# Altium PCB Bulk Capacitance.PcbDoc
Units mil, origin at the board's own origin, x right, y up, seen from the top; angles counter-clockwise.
Board outline 5000 x 5399.89 mil, 4 copper layers (Top Layer, Layer 1, Layer 2, Bottom Layer), stack 91.999 mil thick; 30 components, 6 nets, 116 pads, 1 vias.
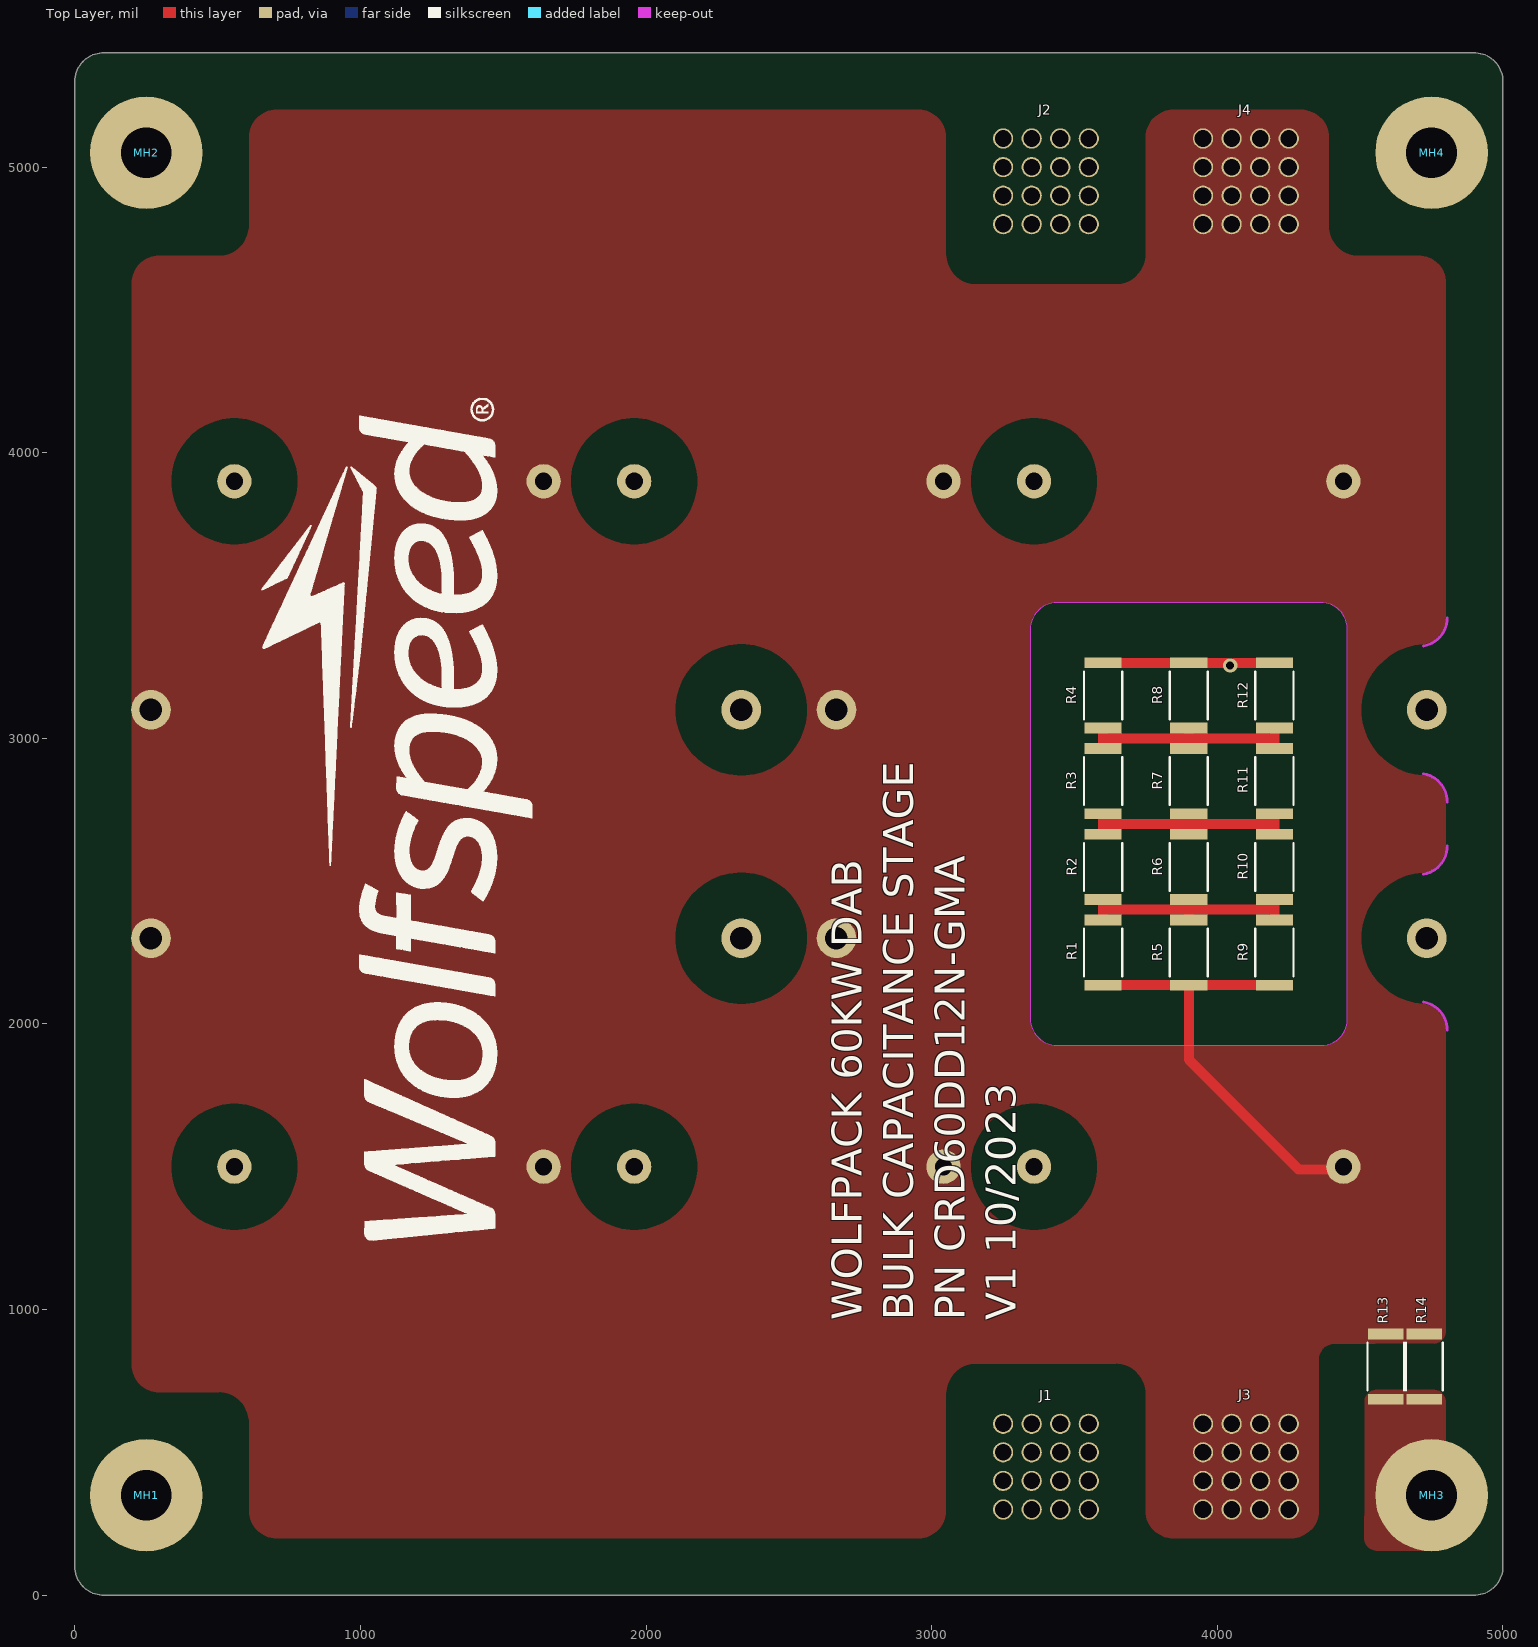
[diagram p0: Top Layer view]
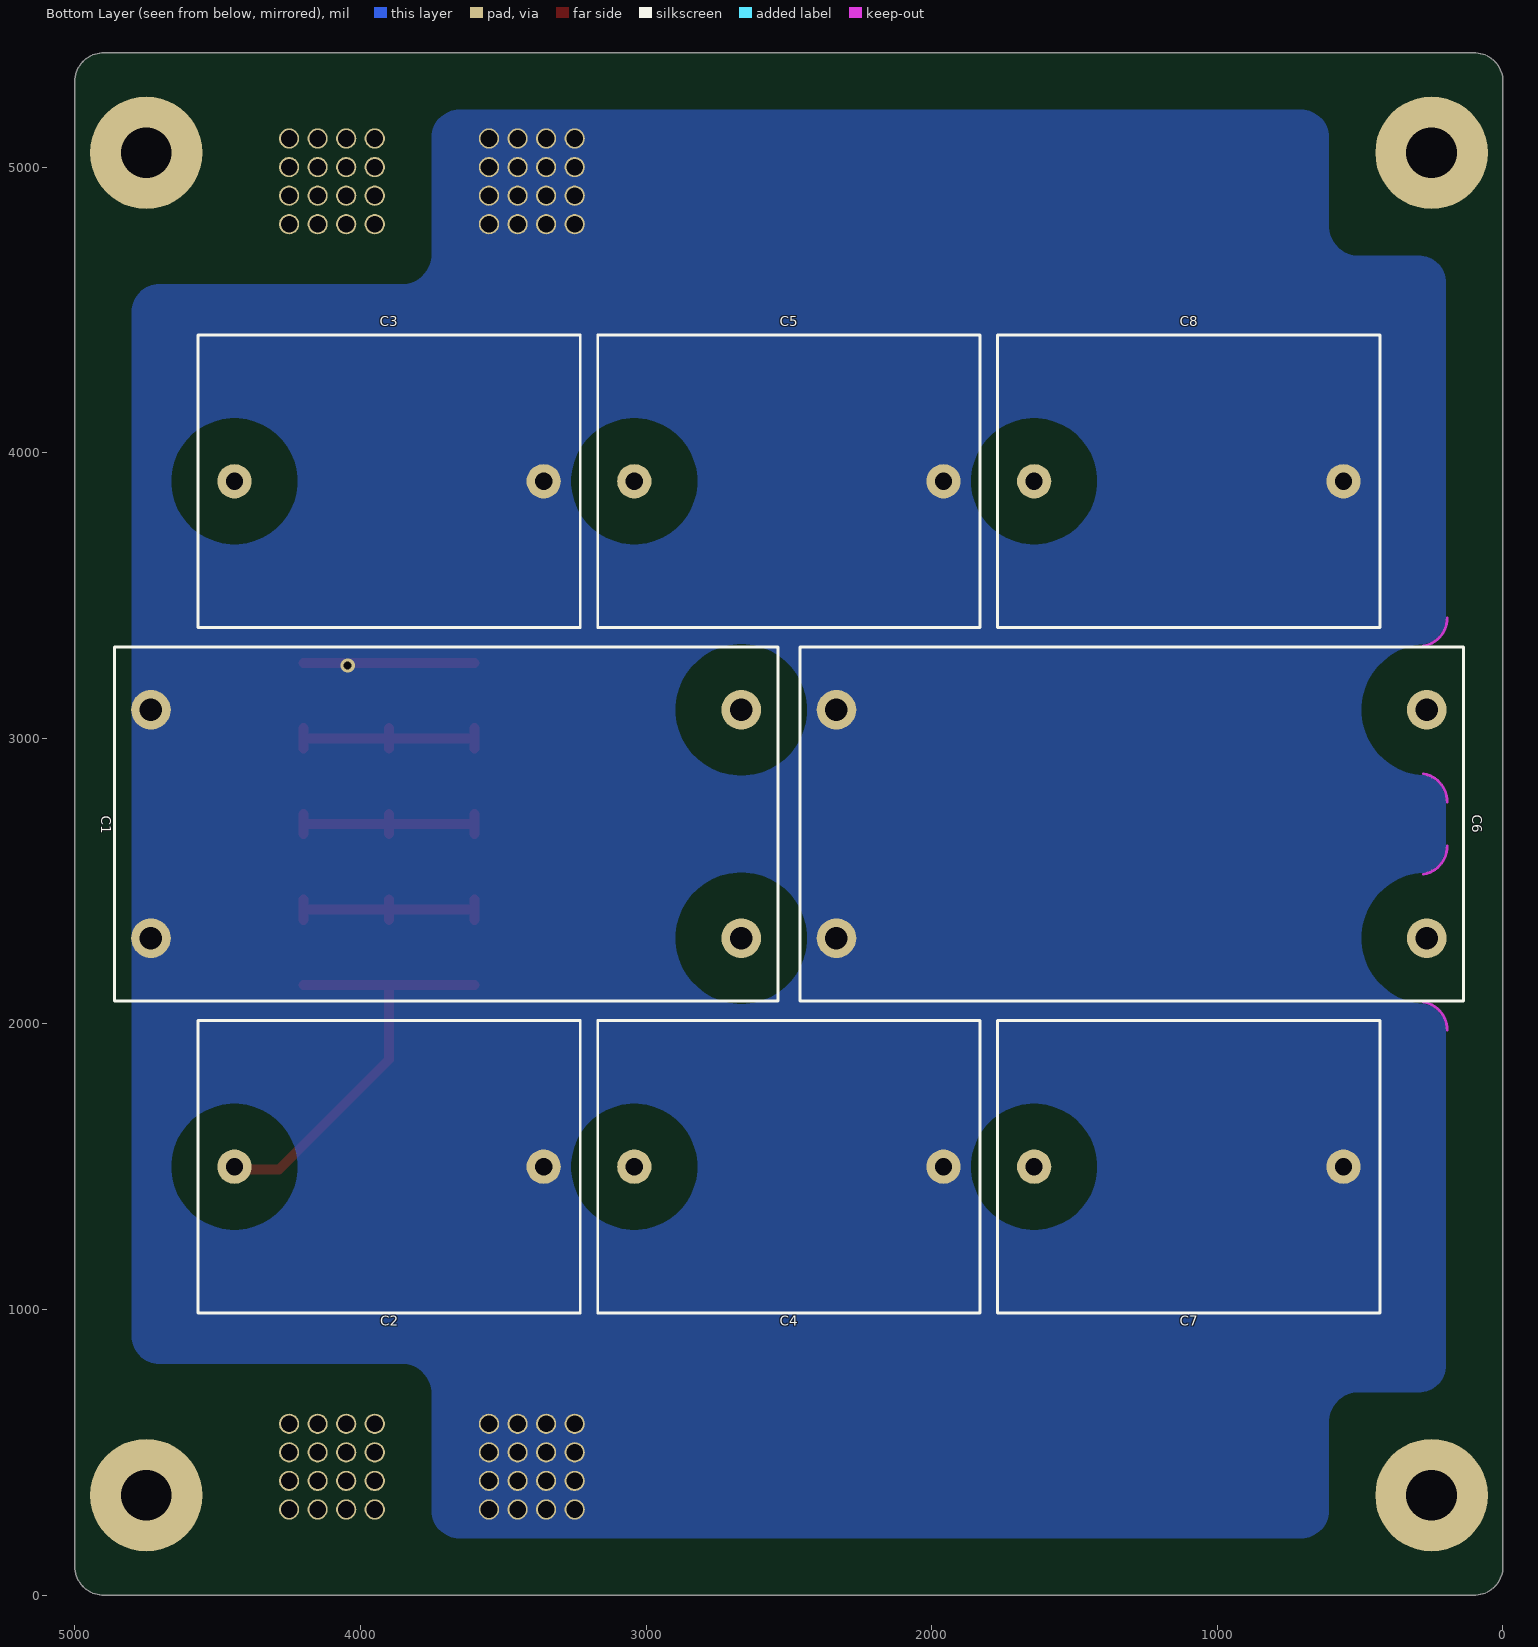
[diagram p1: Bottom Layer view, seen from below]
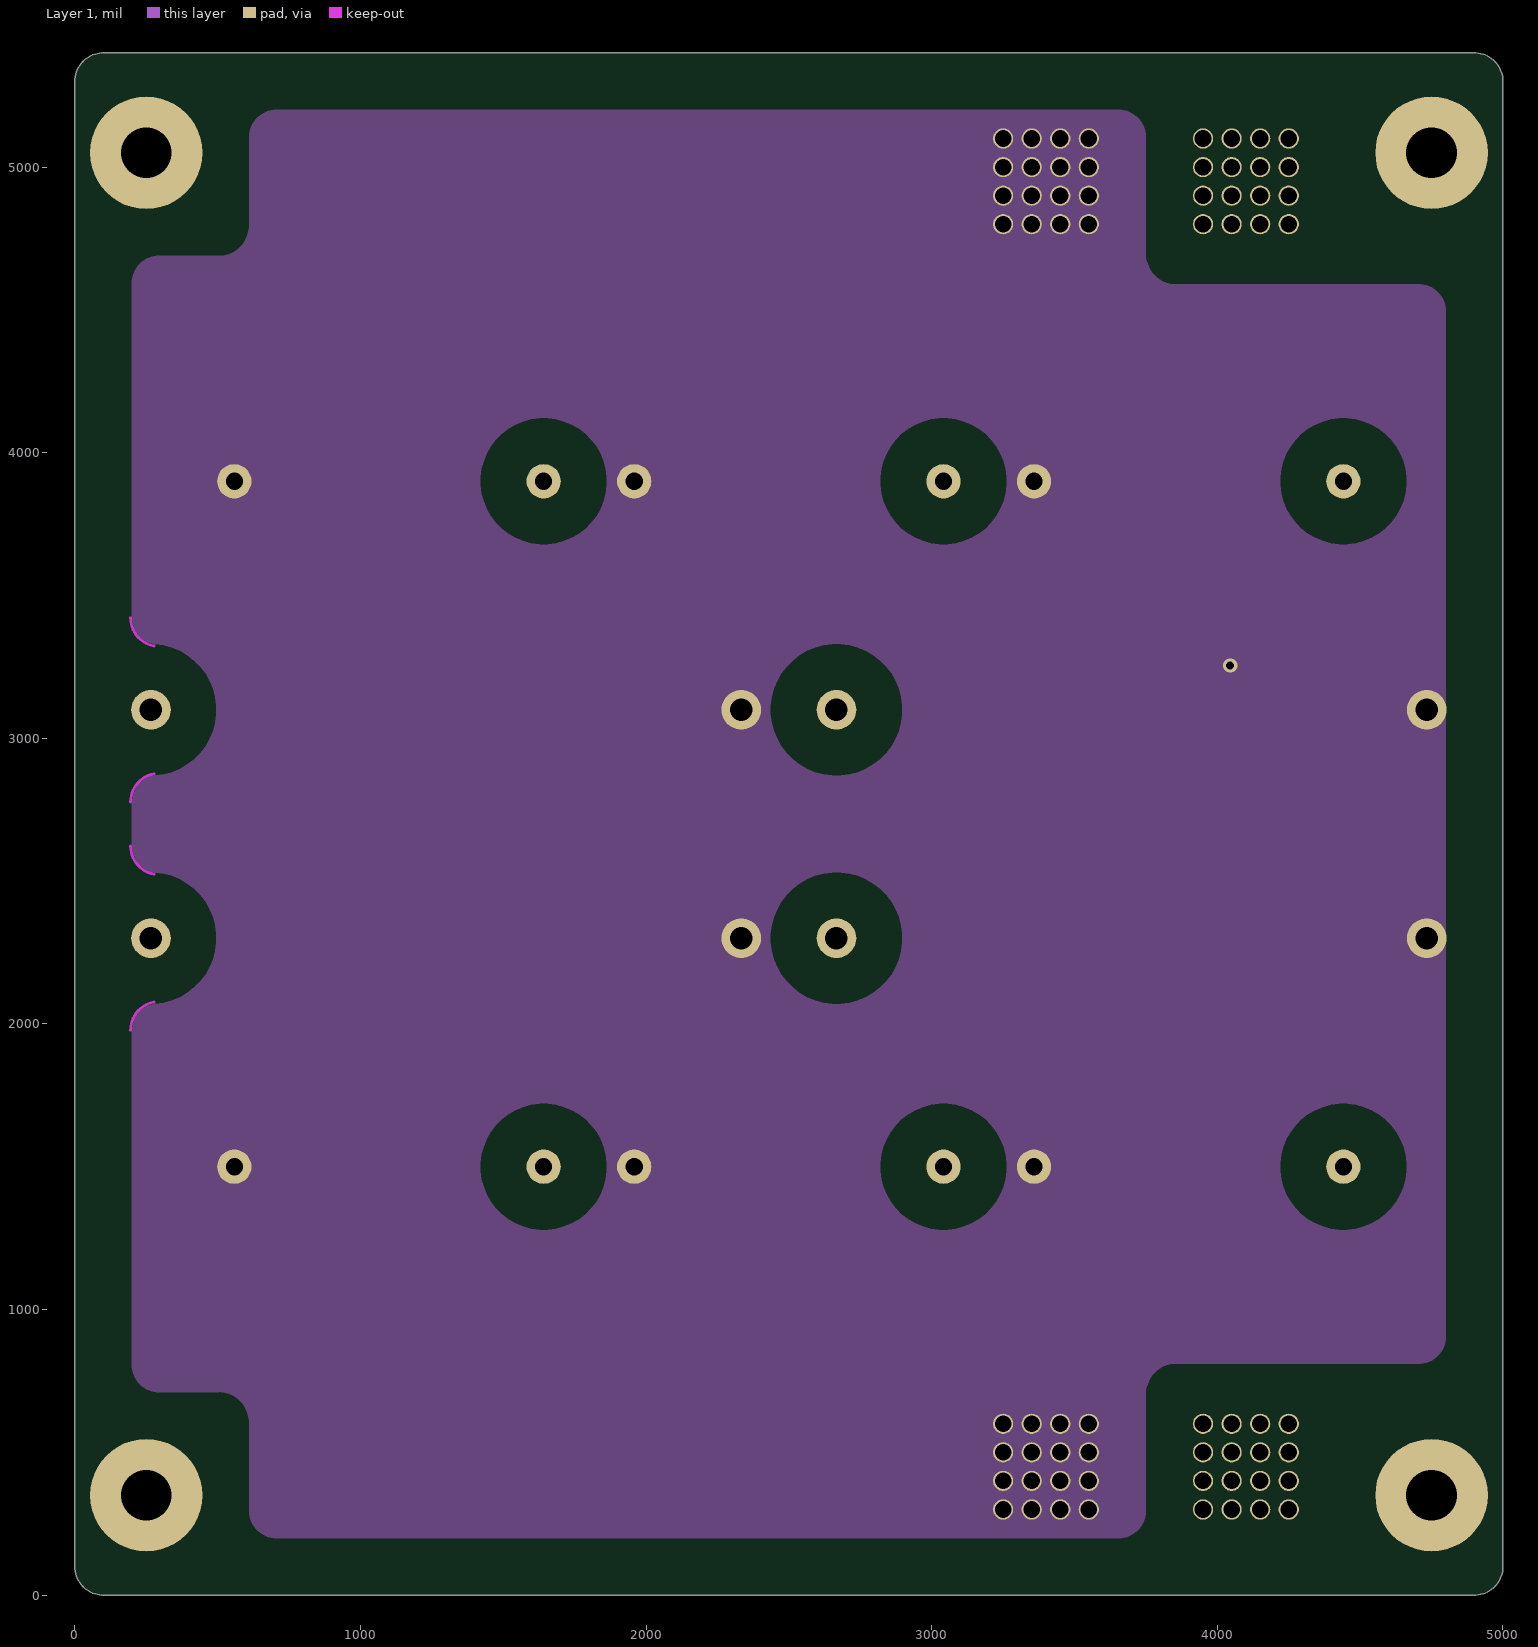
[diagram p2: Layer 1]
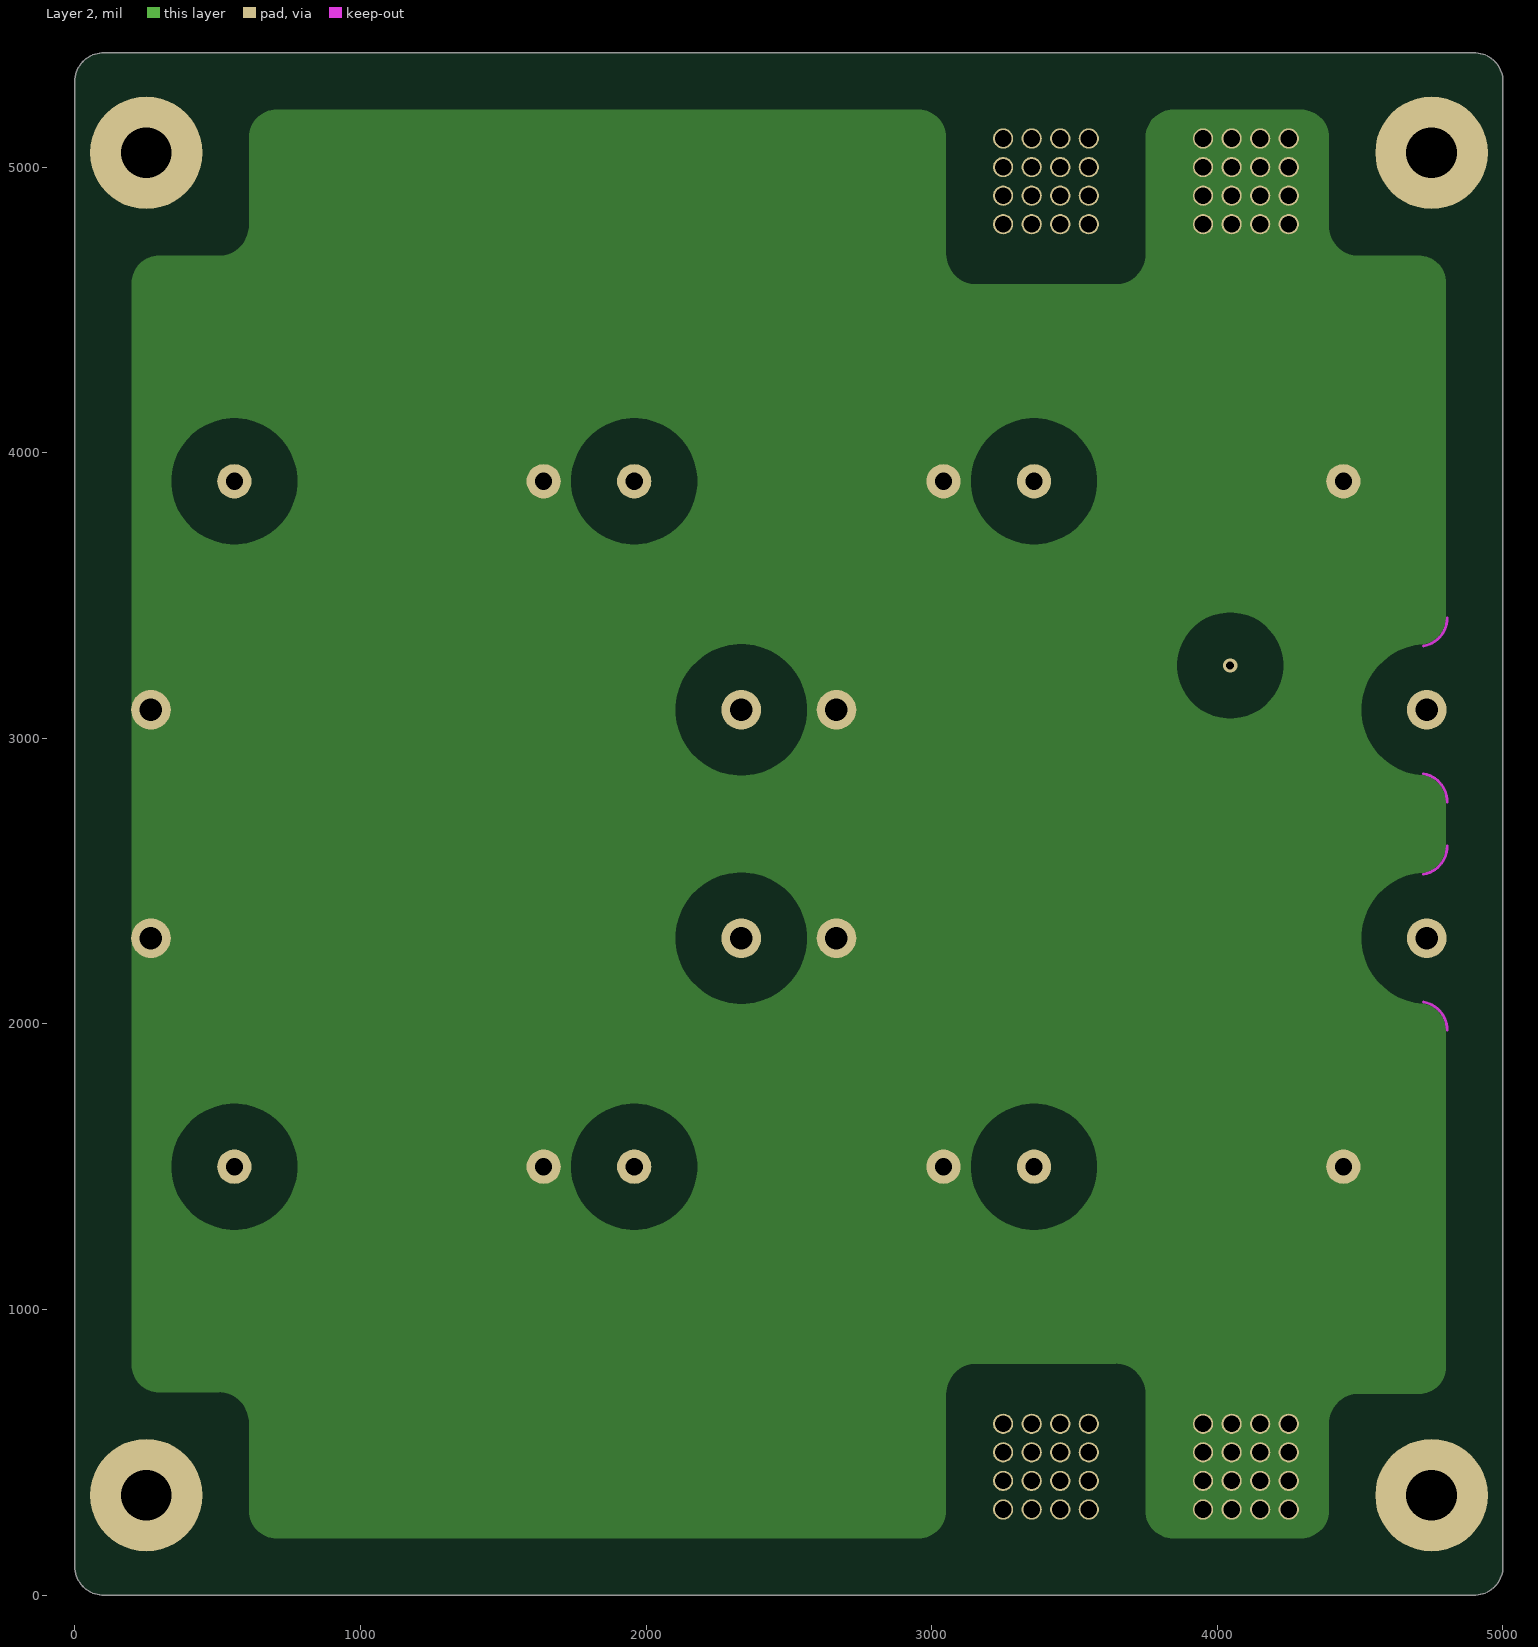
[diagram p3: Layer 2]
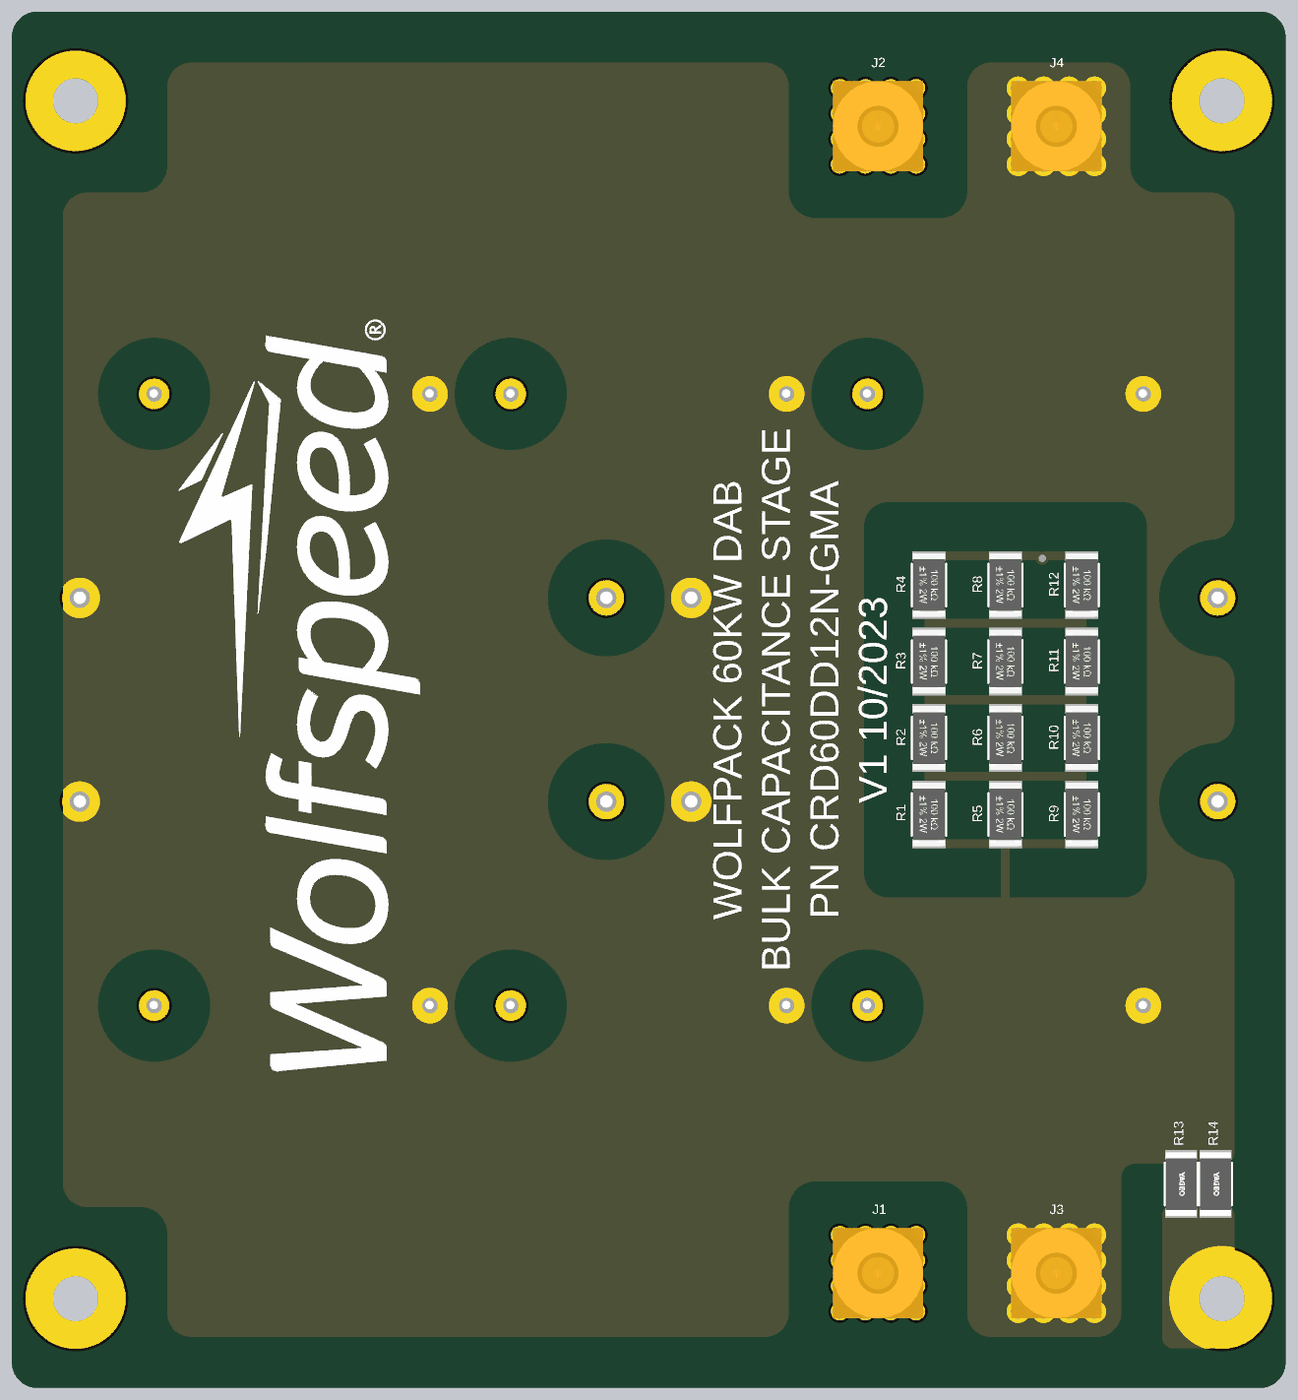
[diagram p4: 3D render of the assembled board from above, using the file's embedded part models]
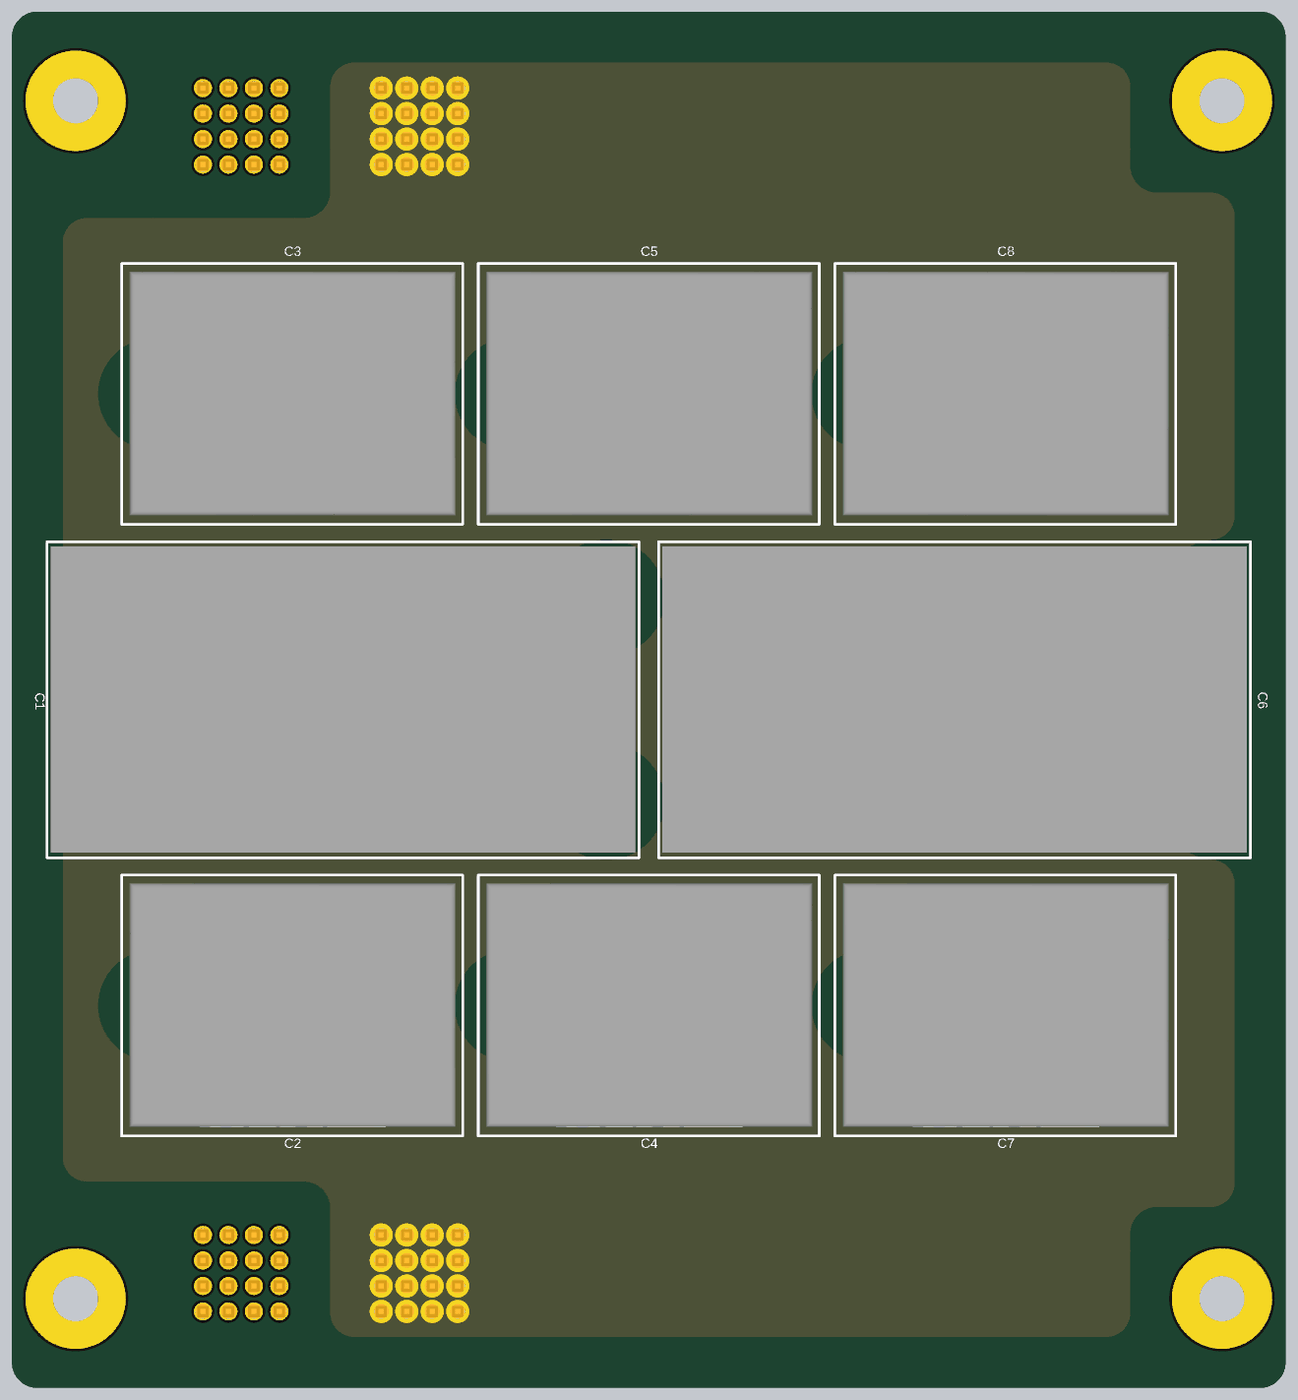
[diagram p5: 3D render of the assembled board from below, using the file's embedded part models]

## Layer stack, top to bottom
Top Solder: solder mask 0.5, Solder Resist, Dk 3.3
Top Layer: signal copper 8.2677
Dielectric 1: prepreg 2.8, PP-006, Dk 4.1
Layer 1: signal copper 8.2677
Dielectric1: core 53.328, FR-4, Dk 4.3
Layer 2: signal copper 8.2677
Dielectric 2: prepreg 2.8, PP-006, Dk 4.1
Bottom Layer: signal copper 8.2677
Bottom Solder: solder mask 0.5, Solder Resist, Dk 3.3

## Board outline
0,100 0,5300 cw(c100,5300) 103.28,5399.95 4896.72,5399.95 cw(c4900,5300) 5000,5300 5000,100 cw(c4900,100) 4896.72,0.05 103.28,0.05 cw(c100,100)

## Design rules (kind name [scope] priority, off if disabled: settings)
Clearance Keepout [IsKeepOut] p1: gap=0 ignorepadtopadclearanceinfootprint=FALSE
Clearance [All] p2: gap=160 ignorepadtopadclearanceinfootprint=FALSE
DiffPairsRouting [All] p1: maxlimit=10 minlimit=10 mostfreqgap=10 toplayer_minwidth=10 toplayer_maxwidth=10 toplayer_prefwidth=10 midlayer1_minwidth=10 midlayer1_maxwidth=10 midlayer1_prefwidth=10 midlayer2_minwidth=10 midlayer2_maxwidth=10 midlayer2_prefwidth=10 bottomlayer_minwidth=10 bottomlayer_maxwidth=10 bottomlayer_prefwidth=10 maxuncoupledlength=500
Height [All] p1: minheight=0 maxheight=2000 prefheight=500
HoleSize [All] p1: absolutevalues=TRUE maxlimit=300 minlimit=10 maxpercent=80.000 minpercent=20.000
MinimumAnnularRing [All] p1: minimumring=6
MinimumSolderMaskSliver [All] p1: minsoldermaskwidth=9
PasteMaskExpansion [All] p1: expansion=10
PlaneClearance [All] p1: clearance=15
PlaneConnect [All] p1: pad.planeconnectstyle=Relief pad.reliefexpansion=20 pad.reliefentries=4 pad.reliefconductorwidth=10 pad.reliefairgap=10 via.planeconnectstyle=Direct via.reliefexpansion=20 via.reliefentries=4 via.reliefconductorwidth=10 via.reliefairgap=10
PolygonConnect [All] p1: connectstyle=Direct reliefconductorwidth=10 reliefentries=4 polygonreliefangle="90 Angle" airgapwidth=10
RoutingVias [All] p1: holewidth=10 width=20 viastyle="Through Hole" minholewidth=10 minwidth=20 maxholewidth=30 maxwidth=50
SMDNeckDown [All] p1: percent=100.000
SilkToSilkClearance [All] p1: silktosilkclearance=9
SilkToSolderMaskClearance SilkscreenOverComponentPads [IsPad] p1: minsilkscreentomaskgap=8 clearancetoexposedcopper=TRUE
SolderMaskExpansion [All] p1: expansion=10 istentingtop=FALSE
Width [All] p1: maxlimit=50 minlimit=10 preferedwidth=10
21 further rules are at their usual default settings.

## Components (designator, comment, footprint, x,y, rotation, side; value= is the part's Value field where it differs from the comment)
C1 "C4AQQBW5240M3MJ" C4AQQBW5240M3MJ 3700,2700 r90 bottom value=24μF (schematic designator C2)
C2 "C4AQQLU4210M12J" C4AQQLU4210M12J 3900,1500 r270 bottom value=2.1μF (schematic designator C5)
C3 "C4AQQLU4210M12J" C4AQQLU4210M12J 3900,3900 r270 bottom value=2.1μF (schematic designator C8)
C4 "C4AQQLU4210M12J" C4AQQLU4210M12J 2500,1500 r270 bottom value=2.1μF
C5 "C4AQQLU4210M12J" C4AQQLU4210M12J 2500,3900 r270 bottom value=2.1μF (schematic designator C7)
C6 "C4AQQBW5240M3MJ" C4AQQBW5240M3MJ 1300,2700 r90 bottom value=24μF (schematic designator C1)
C7 "C4AQQLU4210M12J" C4AQQLU4210M12J 1100,1500 r270 bottom value=2.1μF (schematic designator C3)
C8 "C4AQQLU4210M12J" C4AQQLU4210M12J 1100,3900 r270 bottom value=2.1μF (schematic designator C6)
J1 "7461095" "7461095_chemical surface" 3400,450 r0 top value=N/A
J2 "7461095" "7461095_chemical surface" 3400,4950 r0 top value=N/A (schematic designator J3)
J3 "7461095" "7461095_chemical surface" 4100,450 r0 top value=N/A (schematic designator J2)
J4 "7461095" "7461095_chemical surface" 4100,4950 r0 top value=N/A
MH1 "MH_M4_P" MH_M4_P 250,350 r0 top value=N/A (schematic designator MH3)
MH2 "MH_M4_P" MH_M4_P 250,5050 r0 top value=N/A (schematic designator MH1)
MH3 "MH_M4_P" MH_M4_P 4750,350 r0 top value=N/A (schematic designator MH4)
MH4 "MH_M4_P" MH_M4_P 4750,5050 r0 top value=N/A (schematic designator MH2)
R1 "CRGP2512F220K" FP-CRGP2512-IPC_C 3600,2250 r270 top value=220kΩ (schematic designator R11)
R2 "CRGP2512F220K" FP-CRGP2512-IPC_C 3600,2550 r270 top value=220kΩ (schematic designator R8)
R3 "CRGP2512F220K" FP-CRGP2512-IPC_C 3600,2850 r270 top value=220kΩ (schematic designator R5)
R4 "CRGP2512F220K" FP-CRGP2512-IPC_C 3600,3150 r270 top value=220kΩ (schematic designator R2)
R5 "CRGP2512F220K" FP-CRGP2512-IPC_C 3900,2250 r270 top value=220kΩ (schematic designator R12)
R6 "CRGP2512F220K" FP-CRGP2512-IPC_C 3900,2550 r270 top value=220kΩ (schematic designator R9)
R7 "CRGP2512F220K" FP-CRGP2512-IPC_C 3900,2850 r270 top value=220kΩ (schematic designator R6)
R8 "CRGP2512F220K" FP-CRGP2512-IPC_C 3900,3150 r270 top value=220kΩ (schematic designator R3)
R9 "CRGP2512F220K" FP-CRGP2512-IPC_C 4200,2250 r270 top value=220kΩ (schematic designator R10)
R10 "CRGP2512F220K" FP-CRGP2512-IPC_C 4200,2550 r270 top value=220kΩ (schematic designator R7)
R11 "CRGP2512F220K" FP-CRGP2512-IPC_C 4200,2850 r270 top value=220kΩ (schematic designator R4)
R12 "CRGP2512F220K" FP-CRGP2512-IPC_C 4200,3150 r270 top value=220kΩ (schematic designator R1)
R13 "RC2512JK-070RL" FP-RC2512-0_65-IPC_C 4590,800 r270 top value=0Ω
R14 "RC2512JK-070RL" FP-RC2512-0_65-IPC_C 4725,800 r270 top value=0Ω

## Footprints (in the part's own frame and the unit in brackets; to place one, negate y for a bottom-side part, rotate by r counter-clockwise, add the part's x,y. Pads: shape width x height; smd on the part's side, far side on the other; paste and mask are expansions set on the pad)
"7461095_chemical surface" [mm] "M4, blind 4mm"
  round 1.8 hole 1.475: 1(-3.81,-3.81) 1(-3.81,-1.27) 1(-3.81,1.27) 1(-3.81,3.81) 1(-1.27,-3.81) 1(-1.27,-1.27) 1(-1.27,1.27) 1(-1.27,3.81) 1(1.27,-3.81) 1(1.27,-1.27) 1(1.27,1.27) 1(1.27,3.81) 1(3.81,-3.81) 1(3.81,-1.27) 1(3.81,1.27) 1(3.81,3.81)
  body extent -4.5,-4.5 4.5,4.5, height 7
C4AQQBW5240M3MJ [mm]
  round 3.524 hole 2: 1(-10.15,26.25) 2(10.15,26.25) 3(10.15,-26.25) 4(-10.15,-26.25)
  silkscreen extent -15.75,-29.5 15.75,29.5, body extent -15.23,-29.15 15.28,29.15, height 45.3
C4AQQLU4210M12J [mil]
  round 120 hole 60: 1(0,541.5) 2(0,-541.34)
  silkscreen extent -512,-669 512,669, body extent -480,-638 477,642, height 598
FP-CRGP2512-IPC_C [mil]
  rect 37.72x130.17 smd paste+0 mask+0: 1(-114.25,0) 2(114.25,0)
  silkscreen extent -84,-67 84,67, body extent -137,-71 137,71, height 10
FP-RC2512-0_65-IPC_C [mil]
  rect 37.72x124.34 smd paste+0 mask+0: 1(-114.25,0) 2(114.25,0)
  silkscreen extent -84,-64 84,64, body extent -137,-68 137,68, height 10
MH_M4_P [mm] "M4 plated mounting hole"
  round 10 hole 4.5: 1(0,0)

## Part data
C1 C6: "CAP FILM 24UF 5% 1.1KVDC RADIAL", Case/Package=RADIAL, Manufacturer=KEMET, Supplier Part Number 1=80-C4AQQBW5240M3MJ, Voltage=1.1kV
C2 C3 C4 C5 C7 C8: "CAP FILM 2.1UF 5% 1.1KVDC RADIAL", Case/Package=RADIAL, Manufacturer=KEMET, Supplier Part Number 1=80-C4AQQLU4210M12J, Voltage=1.1kV
J1 J2 J3 J4: library part CMP-03913-18187404-1, "TERM REDCUBE M4 16PIN PCB", Case/Package=N/A, Current Rating=180A, Manufacturer=WURTH, Max Operating Temperature=150°C, Min Operating Temperature=-55°C
MH1 MH2 MH3 MH4: "M4 MOUNTING HOLE (HARDWARE TBD)", Case/Package=M4, Manufacturer=N/A
R1 R2 R3 R4 R5 R6 R7 R8 R9 R10 R11 R12: library part CMP-03211-002966-1, "RES 220K OHM 1% 2W 2512", Ambient Temperature Range High=+70°C, Case/Package=2512, Manufacturer=TE, Power Rating=2W, Resistance=220KΩ, Temperature="-55°C to +155°C", Temperature Coefficient=±100ppm/°C, Temperature Range High=+155°C, Temperature Range Low=-55°C, TOLERANCE=0.01, Voltage Rating=500V
R13 R14: library part CMP-2000-06974-2, "RES SMD 0 OHM JUMPER 1W 2512", Case Code (Imperial)=2512, Case Code (Metric)=6432, Manufacturer=YAGEO, Max Operating Temperature=155°C, Max Power Dissipation=1W, Min Operating Temperature=-55°C, Package Quantity=4000, Resistance=0Ω, Resistance Tolerance=5%, Resistor Type="Thick Film", Temperature Coefficient=200ppm/°C, Voltage Rating=200V

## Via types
v1: diameter 50, hole 28, Top Layer to Bottom Layer, tented both sides, 1 vias

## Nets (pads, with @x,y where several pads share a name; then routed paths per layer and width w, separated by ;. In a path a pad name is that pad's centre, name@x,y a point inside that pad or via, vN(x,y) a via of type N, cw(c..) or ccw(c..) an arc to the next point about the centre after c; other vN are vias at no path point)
DC+: C1.1 C1.2 C2.1 C3.1 C4.1 C5.1 C6.1 C6.2 C7.1 C8.1 J1.1 J2.1 R4.1 R8.1 R12.1 | length 607.7
  Top Layer w35: R4.1 4031.69,3264.25 4040.94,3255 4049.06,3255 4058.31,3264.25 R12.1
  other v1: 4045,3255
DC-: C1.3 C1.4 C2.2 C3.2 C4.2 C5.2 C6.3 C6.4 C7.2 C8.2 J3.1 J4.1 R1.2 R5.2 R9.2 R13.1 R14.1 | length 1565.7
  Top Layer w35: R1.2 R5.2 ; R9.2 R5.2 ; C2.2 4431.34,1490 4285,1490 3900,1875 R5.2
EGND: MH3.1 R13.2 R14.2
NetR1_1: R1.1 R2.2 R5.1 R6.2 R9.1 R10.2 | length 814.5
  Top Layer w35: R1.1 3600,2400 ; R2.2 3600,2400 ; R5.1 3900,2400 ; R6.2 3900,2400 ; R9.1 4200,2400 ; R10.2 4200,2400 ; 3600,2400 3900,2400 ; 3900,2400 4200,2400
NetR2_1: R2.1 R3.2 R6.1 R7.2 R10.1 R11.2 | length 814.5
  Top Layer w35: R2.1 3600,2700 ; R3.2 3600,2700 ; R6.1 3900,2700 ; R7.2 3900,2700 ; R10.1 4200,2700 ; R11.2 4200,2700 ; 3600,2700 3900,2700 ; 3900,2700 4200,2700
NetR3_1: R3.1 R4.2 R7.1 R8.2 R11.1 R12.2 | length 814.5
  Top Layer w35: R3.1 3600,3000 ; R4.2 3600,3000 ; R7.1 3900,3000 ; R8.2 3900,3000 ; R11.1 4200,3000 ; R12.2 4200,3000 ; 3600,3000 3900,3000 ; 3900,3000 4200,3000
pads on no net: MH1.1 MH2.1 MH4.1

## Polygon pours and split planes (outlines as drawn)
DC+ on Layer 1 "NONET_L-01_P-001" (solid, pour order 3): 4705.08,4590.02 cw(c4704.98,4495) 4800,4494.89 4800,905 cw(c4705,905) 4705,810 3854.97,810 ccw(c3854.99,705.01) 3750,704.99 3750,294.98 cw(c3655,295) 3654.97,200 705,200 cw(c704.99,294.99) 610,295 610,605 ccw(c505.01,605.01) 505,710 305,710 295,710 cw(c294.99,804.99) 200,805 200,4595 cw(c295,4595) 295,4690 505,4690 ccw(c505,4795) 610,4795 610,4810 610,5105 cw(c705,5105) 705,5200 767,5200 3654.99,5200 cw(c3655,5105) 3750,5105.01 3750,4695 ccw(c3855,4695) 3854.99,4590
DC+ on Bottom Layer "NONET_L-01_P-001" (solid, pour order 4): 4705.08,4590.02 cw(c4704.98,4495) 4800,4494.89 4800,905 cw(c4705,905) 4705,810 3854.97,810 ccw(c3854.99,705.01) 3750,704.99 3750,294.98 cw(c3655,295) 3654.97,200 705,200 cw(c704.99,294.99) 610,295 610,605 ccw(c505.01,605.01) 505,710 305,710 295,710 cw(c294.99,804.99) 200,805 200,4595 cw(c295,4595) 295,4690 505,4690 ccw(c505,4795) 610,4795 610,4810 610,5105 cw(c705,5105) 705,5200 767,5200 3654.99,5200 cw(c3655,5105) 3750,5105.01 3750,4695 ccw(c3855,4695) 3854.99,4590
DC- on Top Layer "NONET_L-01_P-001" (solid, pour order 0): 4705,4690 cw(c4705,4595) 4800,4595 4800,4585 4800,925 cw(c4755,925) 4755,880 4410,880 ccw(c4410,825) 4355,825 4355,295 cw(c4260.01,294.99) 4260,200 3870,200 3844.02,200 cw(c3844.02,294.02) 3750,294.02 3750,705 ccw(c3645,705) 3645,810 3155,810 ccw(c3154.99,705.01) 3050,705 3050,305 3050,295 cw(c2955.01,294.99) 2955,200 2891,200 705,200 cw(c705,295) 610,295 610,605 ccw(c505.01,605.01) 505,710 305,710 295,710 cw(c295,805) 200,805 200,4595 cw(c295,4595) 295,4690 505,4690 ccw(c505,4795) 610,4795 610,4810 610,5105 cw(c705,5105) 705,5200 767,5200 2955,5200 cw(c2955.01,5105) 3050,5105 3050,5100 3050,4695 ccw(c3155,4695) 3155,4590 3175.19,4590 3645,4590 ccw(c3645.01,4695) 3750,4695 3750,5105 cw(c3845,5105) 3845,5200 4295.43,5200 cw(c4295.23,5105.22) 4390,5105 4390,4794.02 ccw(c4494.02,4794.02) 4494.02,4690 4503.37,4690
EGND on Top Layer "NONET_L-01_P-001" (solid, pour order 6): 4515,200 ccw(c4560,200) 4560,155 4755,155 ccw(c4755,200) 4800,200 4800,675 ccw(c4755.01,675.01) 4755,720 4560,720 ccw(c4559.99,675.01) 4515,675
DC- on Layer 2 "NONET_L-01_P-001" (solid, pour order 2): 4705,4690 cw(c4705,4595) 4800,4595 4800,4585 4800,798.49 cw(c4706.51,798.49) 4706.51,705 4495,705 ccw(c4495,600) 4390,600 4390,305.98 4390,295 cw(c4295,295) 4295,200 3870,200 3844.02,200 cw(c3844.02,294.02) 3750,294.02 3750,705 ccw(c3645,705) 3645,810 3155,810 ccw(c3155,705) 3050,705 3050,305 3050,295 cw(c2955,295) 2955,200 2891,200 705,200 cw(c705,295) 610,295 610,605 ccw(c505,605) 505,710 305,710 295,710 cw(c295,805) 200,805 200,4595 cw(c295,4595) 295,4690 505,4690 ccw(c505,4795) 610,4795 610,4810 610,5105 cw(c705,5105) 705,5200 767,5200 2955,5200 cw(c2955,5105) 3050,5105 3050,5100 3050,4695 ccw(c3155,4695) 3155,4590 3175.19,4590 3645,4590 ccw(c3645.01,4695) 3750,4695 3750,5105 cw(c3845,5105) 3845,5200 4295.43,5200 cw(c4295.22,5105.22) 4390,5105 4390,4794.02 ccw(c4494.02,4794.02) 4494.02,4690 4503.37,4690

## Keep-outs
Top Layer:
  region: 3345,3380 3345,2020 ccw(c3440,2020) 3440,1925 4365,1925 ccw(c4365,2015.01) 4455.01,2015.01 4455.01,3385.58 ccw(c4362.8,3382.79) 4360,3475 3440,3475 ccw(c3439.99,3380.01)
  lines w10: 4722.36,2076.48 cw(c4705,1978) 4805,1978 ; 4722.36,2524.31 ccw(c4705,2622.79) 4805,2622.79 ; 4722.36,2875.69 cw(c4705,2777.21) 4805,2777.21 ; 4722.36,3323.52 ccw(c4705,3422) 4805,3422
Layer 1:
  lines w10: 195,1978 cw(c295,1978) 277.64,2076.48 ; 195,2622.79 ccw(c295,2622.79) 277.64,2524.31 ; 195,2777.21 cw(c295,2777.21) 277.64,2875.69 ; 195,3422 ccw(c295,3422) 277.64,3323.52
Layer 2:
  lines w10: 4722.36,2076.48 cw(c4705,1978) 4805,1978 ; 4722.36,2524.31 ccw(c4705,2622.79) 4805,2622.79 ; 4722.36,2875.69 cw(c4705,2777.21) 4805,2777.21 ; 4722.36,3323.52 ccw(c4705,3422) 4805,3422
Bottom Layer:
  lines w10: 195,1978 cw(c295,1978) 277.64,2076.48 ; 195,2622.79 ccw(c295,2622.79) 277.64,2524.31 ; 195,2777.21 cw(c295,2777.21) 277.64,2875.69 ; 195,3422 ccw(c295,3422) 277.64,3323.52

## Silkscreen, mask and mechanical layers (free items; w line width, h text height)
Top Overlay:
  drawing of 13 lines, arcs and shapes, not listed
  text "WOLFPACK 60KW DAB  / BULK CAPACITANCE STAGE / PN CRD60DD12N-GMA / V1 10/2023" at 3330,963.05 h180 r90
Drill Drawing:
  circle w10: c100.62,6185.83 r33.33
  lines w10: 0,100 ccw(c100,100) 103.28,0.05 4896.72,0.05 ccw(c4900,100) 5000,100 5000,5300 ccw(c4900,5300) 4896.72,5399.95 103.28,5399.95 ccw(c100,5300) 0,5300 0,100 ; 67.29,5719.17 83.96,5719.17 100.62,5702.5 117.29,5719.17 133.96,5719.17 117.29,5735.83 133.96,5752.5 117.29,5752.5 100.62,5769.17 83.96,5752.5 67.29,5752.5 83.96,5735.83 67.29,5719.17 ; 67.29,5852.5 133.96,5852.5 133.96,5919.17 67.29,5919.17 67.29,5852.5 ; 67.29,6069.17 133.96,6069.17 100.62,6002.5 67.29,6069.17 ; 67.29,6302.5 100.62,6319.17 133.96,6302.5 117.29,6335.83 133.96,6369.17 100.62,6352.5 67.29,6369.17 83.96,6335.83 67.29,6302.5
  lines w15: 7.5,5657.5 8965.01,5657.5 ; 7.5,6407.5 8965.01,6407.5 ; 558.38,5507.5 558.38,6557.5 ; 1098.24,5507.5 1098.24,6557.5 ; 2177.92,5507.5 2177.92,6557.5 ; 2683.8,5507.5 2683.8,6557.5 ; 3417.6,5507.5 3417.6,6557.5 ; 4917.15,5507.5 4917.15,6557.5 ; 5507,5507.5 5507,6557.5 ; 6252.8,5507.5 6252.8,6557.5 ; 7586.41,5507.5 7586.41,6557.5 ; 7.5,5507.5 8965.01,5507.5 8965.01,6557.5 7.5,6557.5 7.5,5507.5
  text "THESE HOLES (1.48MM +/- 0.05MM) ARE FOR PRESS-FIT PART. USE 63.0MIL +/- 1MIL DRILLED HOLES. COPPER THICKNESS IN HOLE 25-60UM." at 245,6625 h100
  text "w" at 20.85,6606.66 h200
  text "Symbol" at 97.5,6452.5 h72
  text "Count" at 603.38,6452.5 h72
  text "Hole Size" at 1143.24,6452.5 h72
  text "Plated" at 2222.92,6452.5 h72
  text "Hole Type" at 2728.8,6452.5 h72
  text "Drill Layer Pair" at 3462.6,6452.5 h72
  text "Via/Pad" at 4962.15,6452.5 h72
  text "Pad Shape" at 5552,6452.5 h72
  text "Hole Tolerance (+)" at 6297.8,6452.5 h72
  text "Hole Tolerance (-)" at 7631.41,6452.5 h72
  text "1" at 603.38,6302.5 h60
  text "0.71mm (28.00mil)" at 1143.24,6302.5 h60
  text "PTH" at 2222.92,6302.5 h60
  text "Round" at 2728.8,6302.5 h60
  text "Top Layer - Bottom Layer" at 3462.6,6302.5 h60
  text "Via" at 4962.15,6302.5 h60
  text "Rounded" at 5552,6302.5 h60
  text "0.08mm (3.00mil)" at 6297.8,6302.5 h60
  text "0.08mm (3.00mil)" at 7631.41,6302.5 h60
  text "64" at 603.38,6152.5 h60
  text "1.48mm (58.07mil)" at 1143.24,6152.5 h60
  text "PTH" at 2222.92,6152.5 h60
  text "Round" at 2728.8,6152.5 h60
  text "Top Layer - Bottom Layer" at 3462.6,6152.5 h60
  text "Pad" at 4962.15,6152.5 h60
  text "Rounded" at 5552,6152.5 h60
  text "0.05mm (1.97mil)" at 6297.8,6152.5 h60
  text "0.05mm (1.97mil)" at 7631.41,6152.5 h60
  text "w" at -189.15,6121.66 h200
  text "12" at 603.38,6002.5 h60
  text "1.52mm (60.00mil)" at 1143.24,6002.5 h60
  text "PTH" at 2222.92,6002.5 h60
  text "Round" at 2728.8,6002.5 h60
  text "Top Layer - Bottom Layer" at 3462.6,6002.5 h60
  text "Pad" at 4962.15,6002.5 h60
  text "Rounded" at 5552,6002.5 h60
  text "0.08mm (3.00mil)" at 6297.8,6002.5 h60
  text "0.08mm (3.00mil)" at 7631.41,6002.5 h60
  text "8" at 603.38,5852.5 h60
  text "2.00mm (78.74mil)" at 1143.24,5852.5 h60
  text "PTH" at 2222.92,5852.5 h60
  text "Round" at 2728.8,5852.5 h60
  text "Top Layer - Bottom Layer" at 3462.6,5852.5 h60
  text "Pad" at 4962.15,5852.5 h60
  text "Rounded" at 5552,5852.5 h60
  text "0.08mm (3.00mil)" at 6297.8,5852.5 h60
  text "0.08mm (3.00mil)" at 7631.41,5852.5 h60
  text "4" at 603.38,5702.5 h60
  text "4.50mm (177.17mil)" at 1143.24,5702.5 h60
  text "PTH" at 2222.92,5702.5 h60
  text "Round" at 2728.8,5702.5 h60
  text "Top Layer - Bottom Layer" at 3462.6,5702.5 h60
  text "Pad" at 4962.15,5702.5 h60
  text "Rounded" at 5552,5702.5 h60
  text "0.13mm (5.00mil)" at 6297.8,5702.5 h60
  text "0.13mm (5.00mil)" at 7631.41,5702.5 h60
  text "89 Total" at 603.38,5552.5 h60
Board Outline:
  the board outline again, w10

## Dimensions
0,100 to 5000,100 on Drill Drawing
103.28,0.05 to 103.28,5399.95 on Drill Drawing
